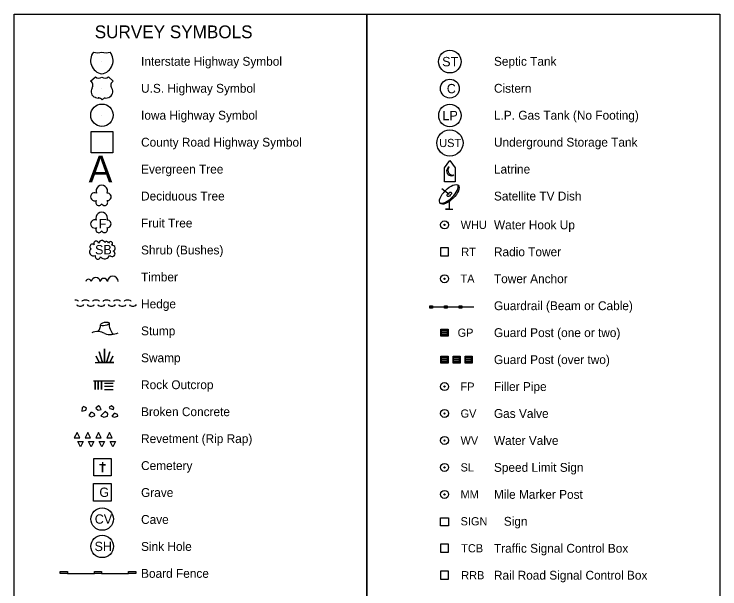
# Model space of a CAD drawing. Extents: x 6082259 to 6083454, y 5964102 to 5966092.
# Drawn here: x 6082259 to 6083454, y 5965119 to 5966092 of the extents above; entities that cross this region are included whole.
import ezdxf

# ---------------------------------------------------------------- set-up
doc = ezdxf.new("R2010")
doc.units = 0
for name, color, linetype in [('Default', 7, 'Continuous'), ('SurControl', 7, 'Continuous'), ('SurPropertyCells', 7, 'Continuous'), ('Text', 7, 'Continuous')]:
    doc.layers.add(name, color=color, linetype=linetype)

msp = doc.modelspace()

# ---------------------------------------------------------------- linework, layer by layer
at = {"layer": 'Default'}
for points in [[(6082259, 5966092.2), (6082856.5, 5966092.2), (6082856.5, 5964102.2), (6082259, 5964102.2)], [(6082856.5, 5966092.2), (6083454, 5966092.2), (6083454, 5964102.2), (6082856.5, 5964102.2)]]:
    msp.add_lwpolyline(points, close=True, dxfattribs=at)
at = {"layer": 'SurPropertyCells'}
msp.add_circle((6082996.8, 5966011.7), 19.2, dxfattribs=at)
at = {"layer": 'Text'}
for p, q in [((6082407.8, 5966012.2), (6082407.8, 5966012.2)), ((6082388.5, 5965978.8), (6082396.6, 5965986)), ((6082418.8, 5965985.9), (6082426.9, 5965978.7)), ((6082391, 5965966.7), (6082391.4, 5965967.3)), ((6082407.8, 5965966.5), (6082407.8, 5965966.5)), ((6082396.7, 5965951), (6082396, 5965951.3)), ((6082402.5, 5965950.1), (6082401.5, 5965950.1)), ((6082407.8, 5965920.9), (6082407.8, 5965920.9)), ((6082995.9, 5965786.9), (6082983.5, 5965796.2)), ((6082412.3, 5965467.3), (6082426.5, 5965467.3)), ((6082412.3, 5965462), (6082426.5, 5965462)), ((6082412.3, 5965456.6), (6082426.5, 5965456.6))]:
    msp.add_line(p, q, dxfattribs=at)
for points in [[(6082389.5, 5965893.5), (6082426, 5965893.5), (6082426, 5965857), (6082389.5, 5965857), (6082389.5, 5965893.5)], [(6082987.8, 5965808.3), (6082987.8, 5965831.8), (6082996.9, 5965844.5), (6083005.9, 5965831.8), (6083005.9, 5965808.3), (6082987.8, 5965808.3)], [(6082995.9, 5965774.5), (6082995.9, 5965762.1), (6082989.7, 5965762.1), (6083002.1, 5965762.1)], [(6082987.8, 5965682.8), (6082987.8, 5965682.8), (6082994.6, 5965682.8), (6082994.6, 5965696.4), (6082981, 5965696.4), (6082981, 5965682.8), (6082987.8, 5965682.8)], [(6082963.2, 5965594.3), (6082963.2, 5965598.4), (6082967.3, 5965598.4), (6082967.3, 5965594.3), (6082963.2, 5965594.3), (6082963.2, 5965595.7), (6082967.3, 5965595.7), (6082967.3, 5965597), (6082963.2, 5965597)], [(6082963.2, 5965596.4), (6083037.5, 5965596.4)], [(6082988, 5965594.3), (6082988, 5965598.4), (6082992.1, 5965598.4), (6082992.1, 5965594.3), (6082988, 5965594.3), (6082988, 5965595.7), (6082992.1, 5965595.7), (6082992.1, 5965597), (6082988, 5965597)], [(6083012.7, 5965594.3), (6083012.7, 5965598.4), (6083016.9, 5965598.4), (6083016.9, 5965594.3), (6083012.7, 5965594.3), (6083012.7, 5965595.7), (6083016.9, 5965595.7), (6083016.9, 5965597), (6083012.7, 5965597)], [(6082982.8, 5965547.7), (6082982.8, 5965557.6), (6082992.7, 5965557.6), (6082992.7, 5965547.7), (6082982.8, 5965547.7), (6082982.8, 5965549.7), (6082992.7, 5965549.7), (6082992.7, 5965551.7), (6082982.8, 5965551.7), (6082982.8, 5965553.7), (6082992.7, 5965553.7), (6082992.7, 5965555.6), (6082982.8, 5965555.6)], [(6082396, 5965502.1), (6082428.1, 5965502.1), (6082421, 5965502.1), (6082426.3, 5965512.8), (6082421, 5965502.1), (6082415.6, 5965502.1), (6082421, 5965520), (6082415.6, 5965502.1), (6082412.1, 5965502.1), (6082412.1, 5965525.3), (6082412.1, 5965502.1), (6082408.5, 5965502.1), (6082403.2, 5965520), (6082408.5, 5965502.1), (6082403.2, 5965502.1), (6082397.8, 5965512.8), (6082403.2, 5965502.1)], [(6082982.8, 5965502.1), (6082982.8, 5965512), (6082992.7, 5965512), (6082992.7, 5965502.1), (6082982.8, 5965502.1), (6082982.8, 5965504.1), (6082992.7, 5965504.1), (6082992.7, 5965506), (6082982.8, 5965506), (6082982.8, 5965508), (6082992.7, 5965508), (6082992.7, 5965510), (6082982.8, 5965510)], [(6083003.2, 5965502.1), (6083003.2, 5965512), (6083013.1, 5965512), (6083013.1, 5965502.1), (6083003.2, 5965502.1), (6083003.2, 5965504.1), (6083013.1, 5965504.1), (6083013.1, 5965506), (6083003.2, 5965506), (6083003.2, 5965508), (6083013.1, 5965508), (6083013.1, 5965510), (6083003.2, 5965510)], [(6083023.5, 5965502.1), (6083023.5, 5965512), (6083033.4, 5965512), (6083033.4, 5965502.1), (6083023.5, 5965502.1), (6083023.5, 5965504.1), (6083033.4, 5965504.1), (6083033.4, 5965506), (6083023.5, 5965506), (6083023.5, 5965508), (6083033.4, 5965508), (6083033.4, 5965510), (6083023.5, 5965510)], [(6082393.5, 5965470.9), (6082396.2, 5965470.9), (6082396.2, 5965456.6), (6082396.2, 5965470.9), (6082401.6, 5965470.9), (6082401.6, 5965456.6), (6082401.6, 5965470.9), (6082406.9, 5965470.9), (6082406.9, 5965456.6), (6082406.9, 5965470.9), (6082429.2, 5965470.9)], [(6082361, 5965374.6), (6082370.2, 5965374.6), (6082365.6, 5965383.8), (6082361, 5965374.6)], [(6082379.3, 5965374.6), (6082388.4, 5965374.6), (6082383.9, 5965383.8), (6082379.3, 5965374.6)], [(6082397.6, 5965374.6), (6082406.7, 5965374.6), (6082402.1, 5965383.8), (6082397.6, 5965374.6)], [(6082415.8, 5965374.6), (6082424.9, 5965374.6), (6082420.4, 5965383.8), (6082415.8, 5965374.6)], [(6082366.7, 5965368.6), (6082375.8, 5965368.6), (6082371.2, 5965359.5), (6082366.7, 5965368.6)], [(6082384.9, 5965368.6), (6082394.1, 5965368.6), (6082389.5, 5965359.5), (6082384.9, 5965368.6)], [(6082403.2, 5965368.6), (6082412.3, 5965368.6), (6082407.8, 5965359.5), (6082403.2, 5965368.6)], [(6082421.5, 5965368.6), (6082430.6, 5965368.6), (6082426, 5965359.5), (6082421.5, 5965368.6)], [(6082393.8, 5965310.2), (6082393.8, 5965339.7), (6082423.4, 5965339.7), (6082423.4, 5965310.2), (6082393.8, 5965310.2)], [(6082408.6, 5965333.3), (6082408.6, 5965316.6), (6082408.6, 5965328.9), (6082413.5, 5965328.9), (6082403.7, 5965328.9)], [(6082987.8, 5965180.8), (6082987.8, 5965180.8), (6082994.6, 5965180.8), (6082994.6, 5965194.3), (6082981, 5965194.3), (6082981, 5965180.8), (6082987.8, 5965180.8)], [(6082349.4, 5965145), (6082395, 5965145)], [(6082407.2, 5965145), (6082452.8, 5965145)], [(6082464.9, 5965145), (6082464.9, 5965145)], [(6082987.8, 5965135.1), (6082987.8, 5965135.1), (6082994.6, 5965135.1), (6082994.6, 5965148.7), (6082981, 5965148.7), (6082981, 5965135.1), (6082987.8, 5965135.1)]]:
    msp.add_lwpolyline(points, dxfattribs=at)
for points in [[(6082981.8, 5965546.7), (6082981.8, 5965558.6), (6082993.7, 5965558.6), (6082993.7, 5965546.7)], [(6082981.8, 5965501.1), (6082981.8, 5965513), (6082993.7, 5965513), (6082993.7, 5965501.1)], [(6083002.2, 5965501.1), (6083002.2, 5965513), (6083014.1, 5965513), (6083014.1, 5965501.1)], [(6083022.5, 5965501.1), (6083022.5, 5965513), (6083034.4, 5965513), (6083034.4, 5965501.1)], [(6082401.7, 5965429), (6082397.3, 5965424.9), (6082401.5, 5965421.3), (6082406.4, 5965422.8), (6082404.3, 5965427.2)], [(6082423.7, 5965428.6), (6082419.9, 5965426.3), (6082421.1, 5965424.2), (6082427.1, 5965422.6), (6082427.9, 5965425.5)], [(6082376.8, 5965427.8), (6082374.2, 5965425.4), (6082373.7, 5965419.7), (6082380.2, 5965421.3), (6082381.5, 5965424.9), (6082379.7, 5965426.2)], [(6082389.2, 5965417.2), (6082385.6, 5965412.5), (6082389.8, 5965410.4), (6082395.5, 5965412.3), (6082394.9, 5965415.1), (6082391.3, 5965417.2)], [(6082413.2, 5965419), (6082406, 5965411.8), (6082410.9, 5965409.4), (6082417.4, 5965411.3), (6082417.6, 5965415.4)], [(6082428.2, 5965416), (6082424.6, 5965411.4), (6082428.7, 5965409.3), (6082434.4, 5965411.1), (6082433.9, 5965413.9), (6082430.3, 5965416)], [(6082393.7, 5965267.5), (6082393.7, 5965297.2), (6082423.5, 5965297.2), (6082423.5, 5965267.5)], [(6082981, 5965225.7), (6082981, 5965239.2), (6082994.6, 5965239.2), (6082994.6, 5965225.7)], [(6082337.2, 5965145), (6082337.2, 5965148.4), (6082349.4, 5965148.4), (6082349.4, 5965145)], [(6082395, 5965145), (6082395, 5965148.4), (6082407.2, 5965148.4), (6082407.2, 5965145)], [(6082452.8, 5965145), (6082452.8, 5965148.4), (6082464.9, 5965148.4), (6082464.9, 5965145)]]:
    msp.add_lwpolyline(points, close=True, dxfattribs=at)
for centre, radius in [((6082996.8, 5965966), 16), ((6082407.8, 5965920.9), 19), ((6082996.9, 5965920.5), 19), ((6082996.9, 5965873.9), 22.2), ((6082987.8, 5965735.2), 6.79), ((6082987.8, 5965735.2), 1.13), ((6082987.8, 5965644), 6.79), ((6082987.8, 5965644), 1.13), ((6082987.8, 5965461.4), 6.79), ((6082987.8, 5965461.4), 1.13), ((6082987.8, 5965415.8), 6.79), ((6082987.8, 5965415.8), 1.13), ((6082987.8, 5965370.1), 6.79), ((6082987.8, 5965370.1), 1.13), ((6082987.8, 5965324.5), 6.79), ((6082987.8, 5965324.5), 1.13), ((6082987.8, 5965278.8), 6.79), ((6082987.8, 5965278.8), 1.13), ((6082408.2, 5965237), 19), ((6082408.2, 5965190.7), 19)]:
    msp.add_circle(centre, radius, dxfattribs=at)
for centre, radius, start, end in [((6082411.4, 5966013.6), 23, 141.2897, 260.377), ((6082401.1, 5966050), 23.3, 250.8344, 286.0898), ((6082414, 5966050), 23.3, 253.9102, 289.1613), ((6082403.7, 5966013.6), 23, 279.623, 38.7204), ((6082414, 5966050), 23.3, 289.1818, 289.185), ((6082384.1, 5965971.6), 8.46, 328.1178, 58.4185), ((6082402.4, 5965992.1), 8.46, 226.652, 308.6604), ((6082413, 5965992.1), 8.46, 230.5703, 313.348), ((6082431.3, 5965971.5), 8.46, 121.5815, 211.8822), ((6082399.6, 5965961), 10.3, 145.8972, 250.3585), ((6082415.8, 5965960.9), 10.3, 289.6415, 34.1028), ((6082403.5, 5965974.1), 24.1, 253.4797, 265.7777), ((6082402.1, 5965943), 7.07, 33.6844, 87.4407), ((6082413.9, 5965942.9), 7.07, 95.8567, 146.3156), ((6082411.9, 5965974.1), 24.1, 274.6642, 286.5203), ((6082999.3, 5965826.4), 7.87, 116.2289, 304.7925), ((6083001.5, 5965827.5), 7.91, 142.8907, 286.2253), ((6082407.5, 5965792.7), 9.75, 338.2051, 201.7949), ((6082395.5, 5965782.8), 6.97, 65.4824, 294.5175), ((6082417, 5965782.8), 6.36, 265.9982, 94.0018), ((6082402.6, 5965773.2), 5.31, 142.7501, 335.3223), ((6082412.2, 5965773.4), 5.3, 206.5242, 35.4033), ((6082407.3, 5965746.8), 9.75, 338.2051, 201.7949), ((6082395.4, 5965736.8), 6.97, 65.4824, 294.5175), ((6082416.8, 5965736.8), 6.36, 265.9982, 94.0018), ((6082402.5, 5965727.3), 5.31, 142.7501, 335.3223), ((6082412.1, 5965727.4), 5.3, 206.5242, 35.4033), ((6082398.1, 5965703.7), 4.12, 10.5948, 214.3611), ((6082407.6, 5965703.1), 5.57, 22.6036, 165.7836), ((6082415.7, 5965704.1), 3.15, 0.4605, 158.7839), ((6082422.3, 5965703.3), 3.57, 311.3936, 166.4114), ((6082393.2, 5965689.4), 6.62, 125.8289, 299.2848), ((6082391.7, 5965698.3), 4.32, 45.3455, 236.8073), ((6082425, 5965695.5), 5.15, 290.9039, 94.3687), ((6082400.8, 5965681.8), 4.68, 157.0258, 349.7602), ((6082412.2, 5965686.7), 8.99, 220.0183, 343.6977), ((6082425.2, 5965686.2), 4.79, 204.8294, 69.8871), ((6082397.2, 5965638.4), 7.66, 5.6097, 174.3903), ((6082410.9, 5965638.4), 6.15, 6.8184, 173.1816), ((6082426.2, 5965639.2), 9.15, 0, 180), ((6082385, 5965638.5), 4.63, 8.8069, 171.1931), ((6082388.6, 5965565.5), 16.7, 319.4836, 1.8241), ((6082444, 5965567.1), 24, 175.4776, 225.2691), ((6082400.1, 5965530.5), 24.2, 58.6739, 113.6979), ((6082422.1, 5965578.6), 29, 251.1942, 296.4339)]:
    msp.add_arc(centre, radius, start, end, dxfattribs=at)
for centre, major_axis, ratio in [((6082995.9, 5965786.9), (-15.3, -15.3), 0.428571), ((6082995.9, 5965786.9), (-3.28, -3.28), 0.5), ((6082412.7, 5965567.5), (-7.43, -1.49), 0.385758)]:
    msp.add_ellipse(centre, major_axis=major_axis, ratio=ratio, dxfattribs=at)
for centre, major_axis, ratio, start_param, end_param in [((6082994.1, 5965788.6), (-15.3, -15.3), 0.428571, 0.159141, 2.993624), ((6082362.1, 5965605.4), (5.94, 0), 0.4, 0, 1.570796), ((6082379.9, 5965605.4), (-5.94, 0), 0.4, 4.712389, 6.283185), ((6082379.9, 5965605.4), (5.94, 0), 0.4, 0, 1.570796), ((6082397.7, 5965605.4), (-5.94, 0), 0.4, 4.712389, 6.283185), ((6082397.7, 5965605.4), (5.94, 0), 0.4, 0, 1.570796), ((6082415.5, 5965605.4), (-5.94, 0), 0.4, 4.712389, 6.283185), ((6082415.5, 5965605.4), (5.94, 0), 0.4, 0, 1.570796), ((6082433.4, 5965605.4), (-5.94, 0), 0.4, 4.712389, 6.283185), ((6082433.4, 5965605.4), (5.94, 0), 0.4, 0, 1.570796), ((6082451.2, 5965605.4), (-5.94, 0), 0.4, 4.712389, 6.283185), ((6082451.2, 5965605.4), (5.94, 0), 0.4, 0, 1.570796), ((6082371, 5965600.1), (-5.94, 0), 0.4, 0, 3.141593), ((6082388.8, 5965600.1), (-5.94, 0), 0.4, 0, 3.141593), ((6082406.6, 5965600.1), (-5.94, 0), 0.4, 0, 3.141593), ((6082424.5, 5965600.1), (-5.94, 0), 0.4, 0, 3.141593), ((6082442.3, 5965600.1), (-5.94, 0), 0.4, 0, 3.141593), ((6082460.1, 5965600.1), (-5.94, 0), 0.4, 0, 3.141593)]:
    msp.add_ellipse(centre, major_axis=major_axis, ratio=ratio, start_param=start_param, end_param=end_param, dxfattribs=at)

# ---------------------------------------------------------------- texts
at = {"layer": 'SurControl'}
for s, height, p in [('SURVEY SYMBOLS', 21.667, (6082395.5, 5966051.3)), ('Interstate Highway Symbol', 15, (6082474, 5966004.7)), ('Septic Tank', 15, (6083071.5, 5966004.7)), ('U.S. Highway Symbol', 15, (6082474, 5965959)), ('Cistern', 15, (6083071.5, 5965959)), ('Iowa Highway Symbol', 15, (6082474, 5965913.4)), ('L.P. Gas Tank (No Footing)', 15, (6083071.5, 5965913.4)), ('County Road Highway Symbol', 15, (6082474, 5965867.7)), ('Underground Storage Tank', 15, (6083071.5, 5965867.7)), ('Evergreen Tree', 15, (6082474, 5965822.1)), ('Latrine', 15, (6083071.5, 5965822.1)), ('Deciduous Tree', 15, (6082474, 5965776.5)), ('Satellite TV Dish', 15, (6083071.5, 5965776.5)), ('Fruit Tree', 15, (6082474, 5965730.8)), ('Water Hook Up', 15, (6083071.5, 5965727.7)), ('Shrub (Bushes)', 15, (6082474, 5965685.2)), ('Radio Tower', 15, (6083071.5, 5965682.1)), ('Timber', 15, (6082474, 5965639.5)), ('Tower Anchor', 15, (6083071.5, 5965636.5)), ('Hedge', 15, (6082474, 5965593.9)), ('Guardrail (Beam or Cable)', 15, (6083071.5, 5965590.8)), ('Stump', 15, (6082474, 5965548.2)), ('Guard Post (one or two)', 15, (6083071.5, 5965545.2)), ('Swamp', 15, (6082474, 5965502.6)), ('Guard Post (over two)', 15, (6083071.5, 5965499.5)), ('Rock Outcrop', 15, (6082474, 5965457)), ('Filler Pipe', 15, (6083071.5, 5965453.9)), ('Broken Concrete', 15, (6082474, 5965411.3)), ('Gas Valve', 15, (6083071.5, 5965408.3)), ('Revetment (Rip Rap)', 15, (6082474, 5965365.7)), ('Water Valve', 15, (6083071.5, 5965362.6)), ('Cemetery', 15, (6082474, 5965320)), ('Speed Limit Sign', 15, (6083071.5, 5965317)), ('Grave', 15, (6082474, 5965274.4)), ('Mile Marker Post', 15, (6083071.5, 5965271.3)), ('Sink Hole', 15, (6082474, 5965183.1)), ('Traffic Signal Control Box', 15, (6083071.5, 5965180)), ('Board Fence', 15, (6082474, 5965137.5)), ('Rail Road Signal Control Box', 15, (6083071.5, 5965134.4))]:
    msp.add_text(s, height=height, dxfattribs=at).set_placement(p)
at = {"layer": 'SurPropertyCells'}
msp.add_text('ST', height=15.99, dxfattribs=at).set_placement((6082983.8, 5966003.7))
at = {"layer": 'Text'}
for s, height, p in [('C', 15.8, (6082991.7, 5965958.1)), ('LP', 15.85, (6082984.3, 5965912.5)), ('UST', 13.87, (6082978.8, 5965867)), ('A', 45.3, (6082385.1, 5965807)), ('F', 15.8, (6082402.3, 5965729.3)), ('WHU', 13.82, (6083015.2, 5965728.3)), ('SB', 15.85, (6082396.1, 5965685.3)), ('RT', 13.87, (6083016.1, 5965682.7)), ('TA', 13.93, (6083014.8, 5965637.2)), ('GP', 13.87, (6083010, 5965545.7)), ('FP', 13.82, (6083015, 5965454.5)), ('GV', 13.82, (6083015, 5965408.8)), ('WV', 13.82, (6083015, 5965363.2)), ('SL', 13.82, (6083015, 5965317.6)), ('G', 15.8, (6082403.4, 5965274.5)), ('MM', 13.82, (6083015, 5965271.9)), ('CV', 15.85, (6082395.6, 5965229.1)), ('Cave', 15, (6082474, 5965228.8)), ('SIGN', 13.87, (6083015, 5965226.3)), ('Sign', 15, (6083088.2, 5965225.7)), ('SH', 15.85, (6082395.3, 5965182.8)), ('TCB', 13.87, (6083016.1, 5965180.6)), ('RRB', 13.87, (6083016.1, 5965135))]:
    msp.add_text(s, height=height, dxfattribs=at).set_placement(p)

doc.saveas('drawing.dxf')
